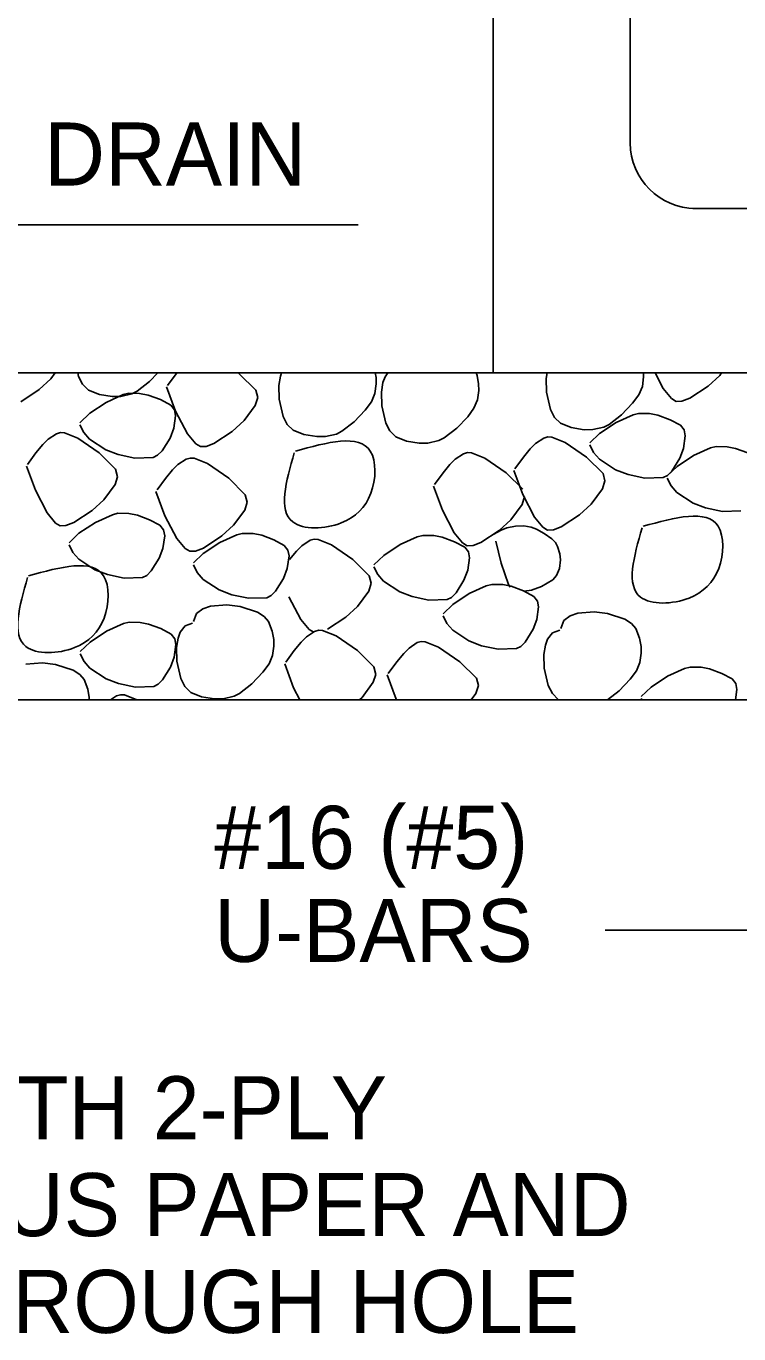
# Model space of a CAD drawing. Extents: x 638455 to 640199, y 298558 to 299152.
# Drawn here: x 639430.1 to 639468.1, y 298625.3 to 298695 of the extents above; entities that cross this region are included whole.
import ezdxf

# ---------------------------------------------------------------- set-up
doc = ezdxf.new("R2010")
doc.units = 0
doc.layers.add('2', color=7, linetype='Continuous')
doc.layers.add('3', color=7, linetype='Continuous')

msp = doc.modelspace()

# ---------------------------------------------------------------- linework, layer by layer
at = {"layer": '2'}
for p, q in [((639462.3, 298747.083), (639462.3, 298688.79)), ((639454.982, 298705.428), (639454.982, 298676.532)), ((639465.635, 298685.305), (639532.432, 298685.305)), ((639454.982, 298676.533), (639414.143, 298676.533)), ((639543.385, 298676.533), (639454.982, 298676.533)), ((639457.422, 298676.533), (639492.275, 298676.533)), ((639522.815, 298659.109), (639414.143, 298659.109)), ((639460.961, 298646.834), (639469.69, 298646.834))]:
    msp.add_line(p, q, dxfattribs=at)
for points in [[(639447.803, 298684.43), (639430.379, 298684.43), (639423.409, 298684.43)], [(639431.64, 298676.533), (639431.411, 298676.225)], [(639432.894, 298676.352), (639432.854, 298676.533)], [(639437.111, 298676.533), (639436.678, 298676.076)], [(639437.64, 298675.873), (639438.093, 298676.492)], [(639438.093, 298676.492), (639438.128, 298676.533)], [(639441.406, 298676.533), (639441.458, 298676.495)], [(639441.458, 298676.495), (639442.338, 298675.618)], [(639443.651, 298676.364), (639443.712, 298676.533)], [(639448.707, 298676.533), (639448.748, 298676.297)], [(639449.229, 298676.335), (639449.381, 298676.533)], [(639454.079, 298676.533), (639454.132, 298676.393)], [(639454.132, 298676.393), (639454.213, 298675.949)], [(639457.823, 298676.236), (639457.869, 298676.533)], [(639463.003, 298676.533), (639463.012, 298676.321)], [(639464.057, 298675.702), (639463.622, 298676.533)], [(639467.074, 298676.405), (639466.45, 298675.827)], [(639467.17, 298676.533), (639467.074, 298676.405)], [(639431.411, 298676.225), (639430.786, 298675.647)], [(639433.109, 298675.934), (639432.894, 298676.352)], [(639433.426, 298675.621), (639433.109, 298675.934)], [(639436.678, 298676.076), (639436.016, 298675.566)], [(639438.061, 298674.5), (639437.582, 298675.789)], [(639443.57, 298675.865), (639443.651, 298676.364)], [(639443.584, 298675.136), (639443.57, 298675.865)], [(639448.759, 298675.949), (639448.69, 298675.444)], [(639448.748, 298676.297), (639448.759, 298675.949)], [(639449.035, 298675.516), (639449.116, 298676.016)], [(639449.116, 298676.016), (639449.229, 298676.335)], [(639454.213, 298675.949), (639454.224, 298675.6)], [(639457.837, 298675.508), (639457.823, 298676.236)], [(639462.942, 298675.815), (639462.751, 298675.371)], [(639463.012, 298676.321), (639462.942, 298675.815)], [(639464.502, 298675.165), (639464.057, 298675.702)], [(639466.45, 298675.827), (639465.469, 298675.182)], [(639430.786, 298675.647), (639429.805, 298675.002)], [(639433.998, 298675.388), (639433.426, 298675.621)], [(639434.678, 298675.278), (639433.998, 298675.388)], [(639434.364, 298674.967), (639435.27, 298675.377)], [(639435.145, 298675.284), (639434.678, 298675.278)], [(639435.726, 298675.417), (639435.145, 298675.284)], [(639435.27, 298675.377), (639435.569, 298675.449)], [(639435.569, 298675.449), (639436.147, 298675.444)], [(639436.016, 298675.566), (639435.726, 298675.417)], [(639436.147, 298675.444), (639436.6, 298675.35)], [(639436.6, 298675.35), (639437.256, 298675.112)], [(639437.256, 298675.112), (639437.805, 298674.813)], [(639442.443, 298675.223), (639442.31, 298674.799)], [(639442.338, 298675.618), (639442.443, 298675.223)], [(639443.802, 298674.212), (639443.584, 298675.136)], [(639448.498, 298675.002), (639448.17, 298674.552)], [(639448.69, 298675.444), (639448.498, 298675.002)], [(639449.05, 298674.787), (639449.035, 298675.516)], [(639454.155, 298675.095), (639453.963, 298674.651)], [(639454.224, 298675.6), (639454.155, 298675.095)], [(639458.055, 298674.584), (639457.837, 298675.508)], [(639462.751, 298675.371), (639462.42, 298674.921)], [(639464.749, 298675.017), (639464.502, 298675.165)], [(639465.053, 298675.025), (639464.749, 298675.017)], [(639465.469, 298675.182), (639465.053, 298675.025)], [(639432.961, 298673.884), (639433.487, 298674.386)], [(639433.487, 298674.386), (639434.364, 298674.967)], [(639437.805, 298674.813), (639438, 298674.566)], [(639438, 298674.566), (639438.061, 298674.256)], [(639438.694, 298673.292), (639438.061, 298674.5)], [(639442.31, 298674.799), (639441.711, 298673.994)], [(639448.17, 298674.552), (639447.586, 298673.936)], [(639449.267, 298673.864), (639449.05, 298674.787)], [(639453.963, 298674.651), (639453.635, 298674.201)], [(639458.267, 298674.163), (639458.055, 298674.584)], [(639461.836, 298674.308), (639461.174, 298673.794)], [(639461.54, 298673.896), (639462.446, 298674.305)], [(639462.42, 298674.921), (639461.836, 298674.308)], [(639462.446, 298674.305), (639462.742, 298674.381)], [(639462.742, 298674.381), (639463.323, 298674.375)], [(639463.323, 298674.375), (639463.776, 298674.279)], [(639433.164, 298673.361), (639432.961, 298673.771)], [(639438.061, 298674.256), (639437.965, 298673.585)], [(639441.711, 298673.994), (639441.087, 298673.417)], [(639444.017, 298673.794), (639443.802, 298674.212)], [(639444.334, 298673.48), (639444.017, 298673.794)], [(639447.586, 298673.936), (639446.921, 298673.425)], [(639449.479, 298673.443), (639449.267, 298673.864)], [(639453.051, 298673.588), (639452.386, 298673.074)], [(639453.635, 298674.201), (639453.051, 298673.588)], [(639458.583, 298673.852), (639458.267, 298674.163)], [(639459.155, 298673.62), (639458.583, 298673.852)], [(639459.835, 298673.507), (639459.155, 298673.62)], [(639460.883, 298673.649), (639460.303, 298673.515)], [(639460.66, 298673.315), (639461.54, 298673.896)], [(639461.174, 298673.794), (639460.883, 298673.649)], [(639463.776, 298674.279), (639464.429, 298674.041)], [(639464.429, 298674.041), (639464.978, 298673.742)], [(639464.978, 298673.742), (639465.176, 298673.495)], [(639430.99, 298672.72), (639431.274, 298673.004)], [(639431.274, 298673.004), (639431.707, 298673.292)], [(639431.707, 298673.292), (639431.925, 298673.353)], [(639431.925, 298673.353), (639432.137, 298673.344)], [(639432.137, 298673.344), (639432.848, 298673.056)], [(639432.848, 298673.056), (639433.986, 298672.278)], [(639433.478, 298673.001), (639433.164, 298673.361)], [(639434.338, 298672.441), (639433.478, 298673.001)], [(639437.765, 298673.056), (639437.341, 298672.377)], [(639437.965, 298673.585), (639437.765, 298673.056)], [(639439.138, 298672.754), (639438.694, 298673.292)], [(639441.087, 298673.417), (639440.105, 298672.772)], [(639444.906, 298673.248), (639444.334, 298673.48)], [(639445.585, 298673.138), (639444.906, 298673.248)], [(639446.05, 298673.146), (639445.585, 298673.138)], [(639446.633, 298673.277), (639446.05, 298673.146)], [(639446.921, 298673.425), (639446.633, 298673.277)], [(639449.796, 298673.132), (639449.479, 298673.443)], [(639450.371, 298672.9), (639449.796, 298673.132)], [(639451.05, 298672.787), (639450.371, 298672.9)], [(639452.099, 298672.929), (639451.515, 298672.795)], [(639452.386, 298673.074), (639452.099, 298672.929)], [(639457.256, 298672.778), (639457.689, 298673.065)], [(639457.689, 298673.065), (639457.904, 298673.126)], [(639457.904, 298673.126), (639458.119, 298673.117)], [(639458.119, 298673.117), (639458.83, 298672.83)], [(639460.303, 298673.515), (639459.835, 298673.507)], [(639460.137, 298672.816), (639460.66, 298673.315)], [(639465.234, 298673.184), (639465.138, 298672.516)], [(639465.176, 298673.495), (639465.234, 298673.184)], [(639430.165, 298671.654), (639430.621, 298672.272)], [(639430.621, 298672.272), (639430.99, 298672.72)], [(639433.986, 298672.278), (639434.866, 298671.401)], [(639435.006, 298672.185), (639434.338, 298672.441)], [(639437.341, 298672.377), (639437.105, 298672.148)], [(639439.385, 298672.606), (639439.138, 298672.754)], [(639439.69, 298672.615), (639439.385, 298672.606)], [(639440.105, 298672.772), (639439.69, 298672.615)], [(639451.515, 298672.795), (639451.05, 298672.787)], [(639452.973, 298671.941), (639453.406, 298672.229)], [(639453.406, 298672.229), (639453.621, 298672.29)], [(639453.621, 298672.29), (639453.832, 298672.281)], [(639453.832, 298672.281), (639454.547, 298671.996)], [(639456.6, 298672.046), (639456.969, 298672.493)], [(639456.969, 298672.493), (639457.256, 298672.778)], [(639458.83, 298672.83), (639459.968, 298672.052)], [(639460.34, 298672.293), (639460.137, 298672.702)], [(639460.654, 298671.933), (639460.34, 298672.293)], [(639465.138, 298672.516), (639464.937, 298671.988)], [(639465.675, 298672.127), (639466.581, 298672.537)], [(639466.581, 298672.537), (639466.88, 298672.609)], [(639466.88, 298672.609), (639467.458, 298672.604)], [(639467.458, 298672.604), (639467.911, 298672.511)], [(639467.911, 298672.511), (639468.567, 298672.272)], [(639430.589, 298670.283), (639430.11, 298671.57)], [(639435.897, 298671.996), (639435.006, 298672.185)], [(639436.876, 298672.025), (639435.897, 298671.996)], [(639437.105, 298672.148), (639436.876, 298672.025)], [(639437.898, 298671.364), (639438.183, 298671.648)], [(639438.183, 298671.648), (639438.618, 298671.936)], [(639438.618, 298671.936), (639438.833, 298671.996)], [(639438.833, 298671.996), (639439.045, 298671.988)], [(639439.045, 298671.988), (639439.76, 298671.703)], [(639439.76, 298671.703), (639440.898, 298670.922)], [(639452.317, 298671.21), (639452.685, 298671.657)], [(639452.685, 298671.657), (639452.973, 298671.941)], [(639454.547, 298671.996), (639455.685, 298671.215)], [(639456.147, 298671.427), (639456.6, 298672.046)], [(639459.968, 298672.052), (639460.848, 298671.175)], [(639461.513, 298671.369), (639460.654, 298671.933)], [(639464.272, 298671.044), (639464.798, 298671.546)], [(639464.937, 298671.988), (639464.516, 298671.308)], [(639464.798, 298671.546), (639465.675, 298672.127)], [(639434.971, 298671.003), (639434.838, 298670.582)], [(639434.866, 298671.401), (639434.971, 298671.003)], [(639437.076, 298670.298), (639437.529, 298670.916)], [(639437.529, 298670.916), (639437.898, 298671.364)], [(639440.898, 298670.922), (639441.778, 298670.045)], [(639451.864, 298670.591), (639452.317, 298671.21)], [(639455.685, 298671.215), (639456.565, 298670.338)], [(639456.568, 298670.057), (639456.092, 298671.343)], [(639460.848, 298671.175), (639460.95, 298670.777)], [(639462.181, 298671.114), (639461.513, 298671.369)], [(639463.073, 298670.925), (639462.181, 298671.114)], [(639464.049, 298670.957), (639463.073, 298670.925)], [(639464.281, 298671.076), (639464.049, 298670.957)], [(639464.475, 298670.521), (639464.272, 298670.931)], [(639464.516, 298671.308), (639464.281, 298671.076)], [(639431.219, 298669.072), (639430.589, 298670.283)], [(639434.838, 298670.582), (639434.239, 298669.775)], [(639437.497, 298668.927), (639437.018, 298670.213)], [(639452.285, 298669.22), (639451.808, 298670.507)], [(639460.817, 298670.356), (639460.221, 298669.549)], [(639460.95, 298670.777), (639460.817, 298670.356)], [(639464.789, 298670.161), (639464.475, 298670.521)], [(639465.649, 298669.601), (639464.789, 298670.161)], [(639434.239, 298669.775), (639433.615, 298669.2)], [(639441.88, 298669.647), (639441.746, 298669.226)], [(639441.778, 298670.045), (639441.88, 298669.647)], [(639456.533, 298669.52), (639455.938, 298668.712)], [(639456.667, 298669.941), (639456.533, 298669.52)], [(639457.201, 298668.846), (639456.568, 298670.057)], [(639460.221, 298669.549), (639459.594, 298668.974)], [(639466.317, 298669.345), (639465.649, 298669.601)], [(639431.666, 298668.535), (639431.219, 298669.072)], [(639433.615, 298669.2), (639432.633, 298668.555)], [(639433.786, 298668.567), (639434.695, 298668.976)], [(639434.695, 298668.976), (639434.991, 298669.052)], [(639434.991, 298669.052), (639435.572, 298669.046)], [(639435.572, 298669.046), (639436.025, 298668.95)], [(639436.025, 298668.95), (639436.678, 298668.712)], [(639436.678, 298668.712), (639437.228, 298668.413)], [(639438.13, 298667.716), (639437.497, 298668.927)], [(639441.746, 298669.226), (639441.15, 298668.419)], [(639452.917, 298668.009), (639452.285, 298669.22)], [(639455.938, 298668.712), (639455.311, 298668.137)], [(639457.645, 298668.308), (639457.201, 298668.846)], [(639459.594, 298668.974), (639458.615, 298668.329)], [(639467.208, 298669.157), (639466.317, 298669.345)], [(639468.187, 298669.186), (639467.208, 298669.157)], [(639431.91, 298668.39), (639431.666, 298668.535)], [(639432.218, 298668.395), (639431.91, 298668.39)], [(639432.633, 298668.555), (639432.218, 298668.395)], [(639432.909, 298667.986), (639433.786, 298668.567)], [(639437.228, 298668.413), (639437.425, 298668.166)], [(639437.425, 298668.166), (639437.483, 298667.855)], [(639441.15, 298668.419), (639440.523, 298667.844)], [(639455.311, 298668.137), (639454.332, 298667.492)], [(639455.023, 298667.937), (639455.412, 298668.16)], [(639455.412, 298668.16), (639455.714, 298668.274)], [(639455.714, 298668.274), (639456.176, 298668.369)], [(639456.176, 298668.369), (639456.629, 298668.387)], [(639456.629, 298668.387), (639457.015, 298668.32)], [(639457.015, 298668.32), (639457.3, 298668.215)], [(639457.3, 298668.215), (639457.715, 298667.98)], [(639457.892, 298668.163), (639457.645, 298668.308)], [(639458.2, 298668.169), (639457.892, 298668.163)], [(639458.615, 298668.329), (639458.2, 298668.169)], [(639432.386, 298667.484), (639432.909, 298667.986)], [(639432.589, 298666.961), (639432.386, 298667.373)], [(639437.483, 298667.855), (639437.387, 298667.185)], [(639438.575, 298667.179), (639438.13, 298667.716)], [(639439.536, 298666.917), (639440.413, 298667.498)], [(639440.523, 298667.844), (639439.542, 298667.199)], [(639440.413, 298667.498), (639441.319, 298667.908)], [(639441.319, 298667.908), (639441.618, 298667.98)], [(639441.618, 298667.98), (639442.196, 298667.974)], [(639442.196, 298667.974), (639442.652, 298667.881)], [(639442.652, 298667.881), (639443.305, 298667.643)], [(639443.305, 298667.643), (639443.854, 298667.344)], [(639443.854, 298667.344), (639444.049, 298667.097)], [(639444.508, 298667.039), (639444.795, 298667.324)], [(639444.795, 298667.324), (639445.228, 298667.614)], [(639445.228, 298667.614), (639445.443, 298667.672)], [(639445.443, 298667.672), (639445.657, 298667.664)], [(639445.657, 298667.664), (639446.369, 298667.379)], [(639446.369, 298667.379), (639447.508, 298666.598)], [(639449.157, 298666.813), (639450.034, 298667.394)], [(639450.034, 298667.394), (639450.943, 298667.803)], [(639450.943, 298667.803), (639451.239, 298667.879)], [(639451.239, 298667.879), (639451.82, 298667.873)], [(639451.82, 298667.873), (639452.273, 298667.777)], [(639452.273, 298667.777), (639452.926, 298667.539)], [(639453.362, 298667.472), (639452.917, 298668.009)], [(639452.926, 298667.539), (639453.475, 298667.24)], [(639453.609, 298667.327), (639453.362, 298667.472)], [(639453.917, 298667.336), (639453.609, 298667.327)], [(639454.332, 298667.492), (639453.917, 298667.336)], [(639455.412, 298666.395), (639455.136, 298667.571)], [(639457.715, 298667.98), (639458.122, 298667.684)], [(639458.122, 298667.684), (639458.307, 298667.489)], [(639458.307, 298667.489), (639458.427, 298667.286)], [(639432.903, 298666.604), (639432.589, 298666.961)], [(639437.187, 298666.659), (639436.766, 298665.979)], [(639437.387, 298667.185), (639437.187, 298666.659)], [(639438.822, 298667.034), (639438.575, 298667.179)], [(639439.129, 298667.042), (639438.822, 298667.034)], [(639439.01, 298666.415), (639439.536, 298666.917)], [(639439.542, 298667.199), (639439.129, 298667.042)], [(639444.11, 298666.784), (639444.014, 298666.116)], [(639444.049, 298667.097), (639444.11, 298666.784)], [(639444.139, 298666.592), (639444.508, 298667.039)], [(639448.634, 298666.311), (639449.157, 298666.813)], [(639453.475, 298667.24), (639453.673, 298666.993)], [(639453.731, 298666.682), (639453.635, 298666.014)], [(639453.673, 298666.993), (639453.731, 298666.682)], [(639458.427, 298667.286), (639458.551, 298666.885)], [(639458.551, 298666.885), (639458.578, 298666.566)], [(639433.763, 298666.04), (639432.903, 298666.604)], [(639434.428, 298665.785), (639433.763, 298666.04)], [(639436.766, 298665.979), (639436.53, 298665.747)], [(639439.217, 298665.892), (639439.01, 298666.302)], [(639444.014, 298666.116), (639443.814, 298665.587)], [(639447.508, 298666.598), (639448.387, 298665.721)], [(639448.838, 298665.788), (639448.634, 298666.2)], [(639453.635, 298666.014), (639453.434, 298665.486)], [(639455.813, 298665.262), (639455.412, 298666.395)], [(639458.525, 298666.11), (639458.374, 298665.741)], [(639458.578, 298666.566), (639458.525, 298666.11)], [(639435.322, 298665.596), (639434.428, 298665.785)], [(639436.298, 298665.625), (639435.322, 298665.596)], [(639436.53, 298665.747), (639436.298, 298665.625)], [(639439.527, 298665.532), (639439.217, 298665.892)], [(639440.387, 298664.969), (639439.527, 298665.532)], [(639443.814, 298665.587), (639443.393, 298664.908)], [(639448.489, 298665.323), (639448.355, 298664.902)], [(639448.387, 298665.721), (639448.489, 298665.323)], [(639449.151, 298665.431), (639448.838, 298665.788)], [(639450.011, 298664.867), (639449.151, 298665.431)], [(639453.434, 298665.486), (639453.013, 298664.806)], [(639454.625, 298665.19), (639454.924, 298665.265)], [(639454.924, 298665.265), (639455.502, 298665.259)], [(639455.502, 298665.259), (639455.955, 298665.164)], [(639455.9, 298665.117), (639455.813, 298665.262)], [(639458.165, 298665.506), (639457.573, 298665.146)], [(639458.374, 298665.741), (639458.165, 298665.506)], [(639441.055, 298664.716), (639440.387, 298664.969)], [(639441.947, 298664.527), (639441.055, 298664.716)], [(639442.925, 298664.556), (639441.947, 298664.527)], [(639443.157, 298664.678), (639442.925, 298664.556)], [(639443.393, 298664.908), (639443.157, 298664.678)], [(639444.74, 298663.392), (639444.107, 298664.603)], [(639448.355, 298664.902), (639447.76, 298664.095)], [(639450.676, 298664.612), (639450.011, 298664.867)], [(639451.57, 298664.423), (639450.676, 298664.612)], [(639452.778, 298664.574), (639452.546, 298664.455)], [(639453.013, 298664.806), (639452.778, 298664.574)], [(639452.842, 298664.199), (639453.719, 298664.78)], [(639453.719, 298664.78), (639454.625, 298665.19)], [(639455.955, 298665.164), (639456.609, 298664.925)], [(639456.609, 298664.925), (639457.16, 298664.626)], [(639457.036, 298664.96), (639456.638, 298664.896)], [(639457.573, 298665.146), (639457.036, 298664.96)], [(639457.16, 298664.626), (639457.355, 298664.379)], [(639439.173, 298663.706), (639439.51, 298663.961)], [(639439.51, 298663.961), (639439.922, 298664.097)], [(639439.922, 298664.097), (639440.796, 298664.167)], [(639440.796, 298664.167), (639441.496, 298664.086)], [(639441.496, 298664.086), (639442.434, 298663.781)], [(639447.76, 298664.095), (639447.133, 298663.52)], [(639452.546, 298664.455), (639451.57, 298664.423)], [(639452.317, 298663.697), (639452.842, 298664.199)], [(639457.416, 298664.069), (639457.317, 298663.401)], [(639457.355, 298664.379), (639457.416, 298664.069)], [(639434.384, 298662.765), (639435.29, 298663.174)], [(639435.29, 298663.174), (639435.589, 298663.247)], [(639435.589, 298663.247), (639436.167, 298663.241)], [(639436.167, 298663.241), (639436.62, 298663.148)], [(639436.62, 298663.148), (639437.277, 298662.91)], [(639438.578, 298663.061), (639438.964, 298663.197)], [(639439.019, 298663.282), (639439.173, 298663.706)], [(639442.434, 298663.781), (639442.786, 298663.552)], [(639442.786, 298663.552), (639443.018, 298663.282)], [(639443.018, 298663.282), (639443.215, 298662.773)], [(639445.184, 298662.855), (639444.74, 298663.392)], [(639447.133, 298663.52), (639446.154, 298662.875)], [(639452.52, 298663.174), (639452.317, 298663.587)], [(639452.834, 298662.817), (639452.52, 298663.174)], [(639457.317, 298663.401), (639457.12, 298662.872)], [(639458.601, 298662.91), (639458.755, 298663.337)], [(639458.755, 298663.337), (639459.091, 298663.589)], [(639459.091, 298663.589), (639459.501, 298663.729)], [(639459.501, 298663.729), (639460.378, 298663.799)], [(639460.378, 298663.799), (639461.078, 298663.717)], [(639461.078, 298663.717), (639462.016, 298663.409)], [(639462.016, 298663.409), (639462.367, 298663.183)], [(639462.367, 298663.183), (639462.6, 298662.91)], [(639433.507, 298662.184), (639434.384, 298662.765)], [(639437.277, 298662.91), (639437.825, 298662.611)], [(639437.825, 298662.611), (639438.02, 298662.364)], [(639438.197, 298662.393), (639438.314, 298662.712)], [(639438.314, 298662.712), (639438.578, 298663.061)], [(639443.215, 298662.773), (639443.294, 298662.326)], [(639444.755, 298662.184), (639445.042, 298662.469)], [(639445.042, 298662.469), (639445.475, 298662.756)], [(639445.431, 298662.71), (639445.184, 298662.855)], [(639445.475, 298662.756), (639445.69, 298662.817)], [(639445.69, 298662.817), (639445.902, 298662.808)], [(639445.902, 298662.808), (639446.616, 298662.521)], [(639446.616, 298662.521), (639447.755, 298661.743)], [(639453.693, 298662.254), (639452.834, 298662.817)], [(639457.12, 298662.872), (639456.696, 298662.193)], [(639457.895, 298662.344), (639458.159, 298662.689)], [(639458.159, 298662.689), (639458.546, 298662.826)], [(639462.6, 298662.91), (639462.797, 298662.402)], [(639432.982, 298661.681), (639433.507, 298662.184)], [(639438.081, 298662.053), (639437.982, 298661.382)], [(639438.02, 298662.364), (639438.081, 298662.053)], [(639438.116, 298661.893), (639438.197, 298662.393)], [(639438.133, 298661.165), (639438.116, 298661.893)], [(639443.305, 298661.978), (639443.236, 298661.472)], [(639443.294, 298662.326), (639443.305, 298661.978)], [(639444.386, 298661.737), (639444.755, 298662.184)], [(639447.755, 298661.743), (639448.634, 298660.866)], [(639450.22, 298661.586), (639450.507, 298661.87)], [(639450.507, 298661.87), (639450.94, 298662.161)], [(639450.94, 298662.161), (639451.155, 298662.222)], [(639451.155, 298662.222), (639451.367, 298662.21)], [(639451.367, 298662.21), (639452.081, 298661.926)], [(639452.081, 298661.926), (639453.22, 298661.144)], [(639454.361, 298661.998), (639453.693, 298662.254)], [(639455.252, 298661.809), (639454.361, 298661.998)], [(639456.231, 298661.841), (639455.252, 298661.809)], [(639456.461, 298661.96), (639456.231, 298661.841)], [(639456.696, 298662.193), (639456.461, 298661.96)], [(639457.698, 298661.522), (639457.779, 298662.024)], [(639457.779, 298662.024), (639457.895, 298662.344)], [(639462.797, 298662.402), (639462.875, 298661.955)], [(639462.875, 298661.955), (639462.887, 298661.606)], [(639430.084, 298661.014), (639430.961, 298661.08)], [(639430.961, 298661.08), (639431.66, 298661.002)], [(639433.185, 298661.159), (639432.982, 298661.568)], [(639433.499, 298660.799), (639433.185, 298661.159)], [(639437.982, 298661.382), (639437.785, 298660.854)], [(639438.348, 298660.241), (639438.133, 298661.165)], [(639443.236, 298661.472), (639443.044, 298661.028)], [(639443.933, 298661.118), (639444.386, 298661.737)], [(639449.398, 298660.523), (639449.851, 298661.142)], [(639449.851, 298661.142), (639450.22, 298661.586)], [(639453.22, 298661.144), (639454.1, 298660.267)], [(639457.715, 298660.793), (639457.698, 298661.522)], [(639462.817, 298661.101), (639462.626, 298660.659)], [(639462.887, 298661.606), (639462.817, 298661.101)], [(639431.66, 298661.002), (639432.598, 298660.694)], [(639432.598, 298660.694), (639432.95, 298660.465)], [(639432.95, 298660.465), (639433.182, 298660.195)], [(639434.358, 298660.238), (639433.499, 298660.799)], [(639437.785, 298660.854), (639437.361, 298660.174)], [(639442.716, 298660.578), (639442.132, 298659.965)], [(639443.044, 298661.028), (639442.716, 298660.578)], [(639444.354, 298659.748), (639443.878, 298661.034)], [(639448.736, 298660.467), (639448.602, 298660.046)], [(639448.634, 298660.866), (639448.736, 298660.467)], [(639449.819, 298659.152), (639449.343, 298660.439)], [(639457.93, 298659.869), (639457.715, 298660.793)], [(639462.626, 298660.659), (639462.297, 298660.209)], [(639463.413, 298659.794), (639464.29, 298660.378)], [(639464.29, 298660.378), (639465.196, 298660.787)], [(639465.196, 298660.787), (639465.495, 298660.86)], [(639465.495, 298660.86), (639466.073, 298660.854)], [(639466.073, 298660.854), (639466.526, 298660.761)], [(639466.526, 298660.761), (639467.179, 298660.52)], [(639467.179, 298660.52), (639467.731, 298660.224)], [(639433.182, 298660.195), (639433.38, 298659.686)], [(639433.38, 298659.686), (639433.458, 298659.239)], [(639435.026, 298659.983), (639434.358, 298660.238)], [(639435.918, 298659.794), (639435.026, 298659.983)], [(639436.896, 298659.823), (639435.918, 298659.794)], [(639437.126, 298659.945), (639436.896, 298659.823)], [(639437.361, 298660.174), (639437.126, 298659.945)], [(639438.563, 298659.82), (639438.348, 298660.241)], [(639438.88, 298659.509), (639438.563, 298659.82)], [(639442.132, 298659.965), (639441.467, 298659.451)], [(639444.688, 298659.109), (639444.354, 298659.748)], [(639448.602, 298660.046), (639448.007, 298659.239)], [(639454.201, 298659.872), (639454.068, 298659.448)], [(639454.1, 298660.267), (639454.201, 298659.872)], [(639458.145, 298659.451), (639457.93, 298659.869)], [(639462.297, 298660.209), (639461.714, 298659.594)], [(639462.887, 298659.294), (639463.413, 298659.794)], [(639467.731, 298660.224), (639467.926, 298659.977)], [(639467.987, 298659.663), (639467.905, 298659.109)], [(639467.926, 298659.977), (639467.987, 298659.663)], [(639433.458, 298659.239), (639433.464, 298659.109)], [(639434.599, 298659.109), (639434.919, 298659.32)], [(639434.919, 298659.32), (639435.133, 298659.382)], [(639435.133, 298659.382), (639435.346, 298659.37)], [(639435.346, 298659.37), (639436.002, 298659.109)], [(639439.452, 298659.277), (639438.88, 298659.509)], [(639440.132, 298659.164), (639439.452, 298659.277)], [(639440.596, 298659.173), (639440.132, 298659.164)], [(639441.18, 298659.306), (639440.596, 298659.173)], [(639441.467, 298659.451), (639441.18, 298659.306)], [(639448.007, 298659.239), (639447.865, 298659.109)], [(639449.842, 298659.109), (639449.819, 298659.152)], [(639454.068, 298659.448), (639453.815, 298659.109)], [(639458.461, 298659.138), (639458.145, 298659.451)], [(639458.534, 298659.109), (639458.461, 298659.138)], [(639461.714, 298659.594), (639461.084, 298659.109)], [(639462.925, 298659.109), (639462.887, 298659.181)]]:
    msp.add_lwpolyline(points, dxfattribs=at)
msp.add_arc((639465.785, 298688.79), 3.485, 180, 270, dxfattribs=at)
for points in [[(639444.447, 298672.368), (639448.443, 298672.368), (639448.472, 298670.118), (639446.895, 298668.541), (639444.304, 298668.596), (639444.389, 298672.284)], [(639462.983, 298668.364), (639466.982, 298668.364), (639467.011, 298666.113), (639465.434, 298664.536), (639462.844, 298664.591), (639462.928, 298668.279)], [(639430.226, 298665.721), (639434.225, 298665.721), (639434.251, 298663.47), (639432.677, 298661.893), (639430.086, 298661.949), (639430.171, 298665.637)]]:
    msp.add_spline(points, degree=3, dxfattribs=at)

# ---------------------------------------------------------------- texts
at = {"layer": '3'}
for s, p in [('DRAIN', (639431.053, 298686.522)), ('#16 (#5)', (639440.123, 298650.104)), ('U-BARS', (639440.123, 298645.144)), ('COVER WITH 2-PLY', (639406.893, 298635.689)), ('BITUMINOUS PAPER AND', (639406.893, 298630.529)), ('BREAK THROUGH HOLE', (639406.893, 298625.369))]:
    msp.add_text(s, height=3.36, dxfattribs=at).set_placement(p)

doc.saveas('drawing.dxf')
